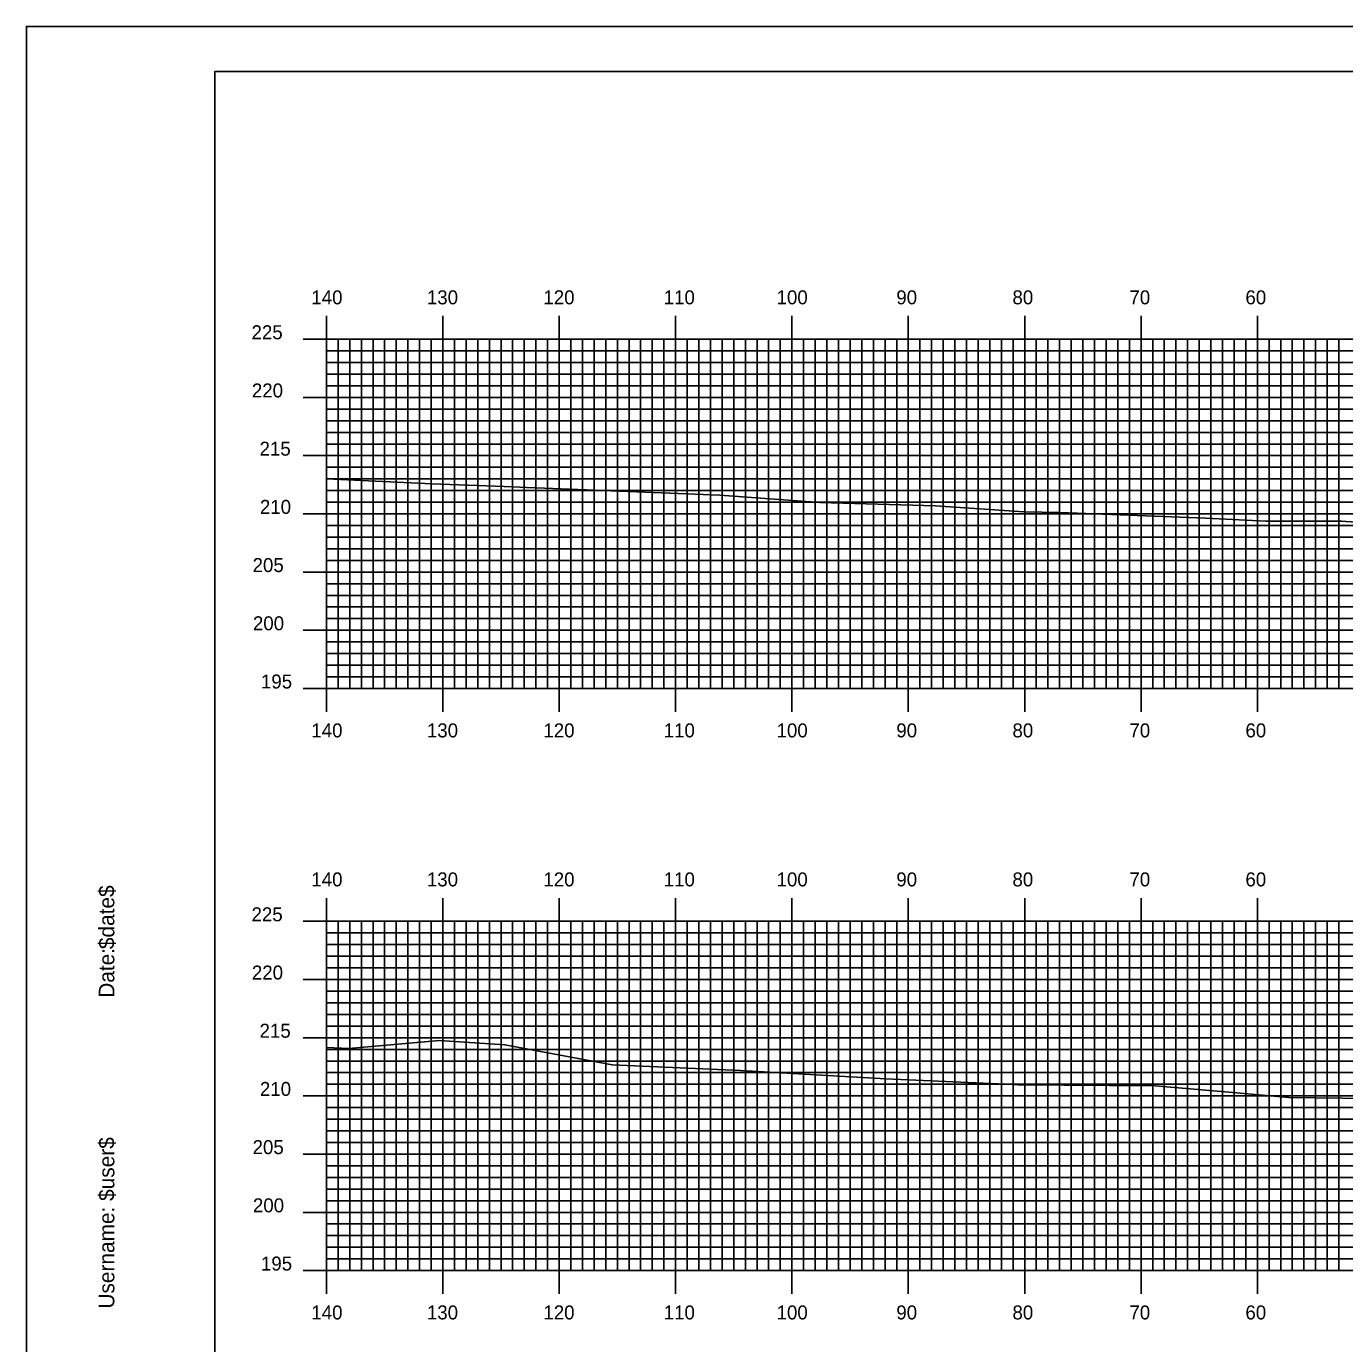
# Model space of a CAD drawing. Extents: x 1805471 to 1805814, y 442591 to 442811.
# Drawn here: x 1805470.9 to 1805584.2, y 442697.4 to 442810.5 of the extents above; entities that cross this region are included whole.
import ezdxf

# ---------------------------------------------------------------- set-up
doc = ezdxf.new("R2010")
doc.units = 0
for name, color, linetype in [('BORDER', 7, 'Continuous'), ('H_V ANNOTATION', 7, 'Continuous'), ('MAJOR', 7, 'Continuous'), ('MINOR', 7, 'Continuous'), ('PLOT BOUNDARY', 7, 'Continuous'), ('S_Roadway_Centerline', 7, 'Continuous')]:
    doc.layers.add(name, color=color, linetype=linetype)

msp = doc.modelspace()

# ---------------------------------------------------------------- linework, layer by layer
at = {"layer": 'BORDER'}
msp.add_lwpolyline([(1805487.11, 442596.67), (1805807.11, 442596.67), (1805807.11, 442806.67), (1805487.11, 442806.67)], close=True, dxfattribs=at)
at = {"layer": 'MAJOR'}
for p, q in [((1805496.71, 442785.67), (1805496.71, 442783.67)), ((1805506.71, 442785.67), (1805506.71, 442783.67)), ((1805516.71, 442785.67), (1805516.71, 442783.67)), ((1805526.71, 442785.67), (1805526.71, 442783.67)), ((1805536.71, 442785.67), (1805536.71, 442783.67)), ((1805546.71, 442785.67), (1805546.71, 442783.67)), ((1805556.71, 442785.67), (1805556.71, 442783.67)), ((1805566.71, 442785.67), (1805566.71, 442783.67)), ((1805576.71, 442785.67), (1805576.71, 442783.67)), ((1805494.7, 442783.67), (1805496.71, 442783.67)), ((1805496.71, 442783.67), (1805776.71, 442783.67)), ((1805496.71, 442753.67), (1805496.71, 442783.67)), ((1805496.71, 442753.67), (1805496.71, 442783.67)), ((1805496.71, 442783.67), (1805776.71, 442783.67)), ((1805506.71, 442753.67), (1805506.71, 442783.67)), ((1805516.71, 442753.67), (1805516.71, 442783.67)), ((1805526.71, 442753.67), (1805526.71, 442783.67)), ((1805536.71, 442753.67), (1805536.71, 442783.67)), ((1805546.71, 442753.67), (1805546.71, 442783.67)), ((1805556.71, 442753.67), (1805556.71, 442783.67)), ((1805566.71, 442753.67), (1805566.71, 442783.67)), ((1805576.71, 442753.67), (1805576.71, 442783.67)), ((1805494.7, 442778.67), (1805496.71, 442778.67)), ((1805496.71, 442778.67), (1805776.71, 442778.67)), ((1805494.7, 442773.67), (1805496.71, 442773.67)), ((1805496.71, 442773.67), (1805776.71, 442773.67)), ((1805494.7, 442768.67), (1805496.71, 442768.67)), ((1805496.71, 442768.67), (1805776.71, 442768.67)), ((1805494.7, 442763.67), (1805496.71, 442763.67)), ((1805496.71, 442763.67), (1805776.71, 442763.67)), ((1805494.7, 442758.67), (1805496.71, 442758.67)), ((1805496.71, 442758.67), (1805776.71, 442758.67)), ((1805494.7, 442753.67), (1805496.71, 442753.67)), ((1805496.71, 442753.67), (1805776.71, 442753.67)), ((1805496.71, 442753.67), (1805776.71, 442753.67)), ((1805496.71, 442751.66), (1805496.71, 442753.67)), ((1805506.71, 442751.66), (1805506.71, 442753.67)), ((1805516.71, 442751.66), (1805516.71, 442753.67)), ((1805526.71, 442751.66), (1805526.71, 442753.67)), ((1805536.71, 442751.66), (1805536.71, 442753.67)), ((1805546.71, 442751.66), (1805546.71, 442753.67)), ((1805556.71, 442751.66), (1805556.71, 442753.67)), ((1805566.71, 442751.66), (1805566.71, 442753.67)), ((1805576.71, 442751.66), (1805576.71, 442753.67)), ((1805496.71, 442735.67), (1805496.71, 442733.67)), ((1805506.71, 442735.67), (1805506.71, 442733.67)), ((1805516.71, 442735.67), (1805516.71, 442733.67)), ((1805526.71, 442735.67), (1805526.71, 442733.67)), ((1805536.71, 442735.67), (1805536.71, 442733.67)), ((1805546.71, 442735.67), (1805546.71, 442733.67)), ((1805556.71, 442735.67), (1805556.71, 442733.67)), ((1805566.71, 442735.67), (1805566.71, 442733.67)), ((1805576.71, 442735.67), (1805576.71, 442733.67)), ((1805494.7, 442733.67), (1805496.71, 442733.67)), ((1805496.71, 442733.67), (1805776.71, 442733.67)), ((1805496.71, 442703.67), (1805496.71, 442733.67)), ((1805496.71, 442703.67), (1805496.71, 442733.67)), ((1805496.71, 442733.67), (1805776.71, 442733.67)), ((1805506.71, 442703.67), (1805506.71, 442733.67)), ((1805516.71, 442703.67), (1805516.71, 442733.67)), ((1805526.71, 442703.67), (1805526.71, 442733.67)), ((1805536.71, 442703.67), (1805536.71, 442733.67)), ((1805546.71, 442703.67), (1805546.71, 442733.67)), ((1805556.71, 442703.67), (1805556.71, 442733.67)), ((1805566.71, 442703.67), (1805566.71, 442733.67)), ((1805576.71, 442703.67), (1805576.71, 442733.67)), ((1805494.7, 442728.67), (1805496.71, 442728.67)), ((1805496.71, 442728.67), (1805776.71, 442728.67)), ((1805494.7, 442723.67), (1805496.71, 442723.67)), ((1805496.71, 442723.67), (1805776.71, 442723.67)), ((1805494.7, 442718.67), (1805496.71, 442718.67)), ((1805496.71, 442718.67), (1805776.71, 442718.67)), ((1805494.7, 442713.67), (1805496.71, 442713.67)), ((1805496.71, 442713.67), (1805776.71, 442713.67)), ((1805494.7, 442708.67), (1805496.71, 442708.67)), ((1805496.71, 442708.67), (1805776.71, 442708.67)), ((1805494.7, 442703.67), (1805496.71, 442703.67)), ((1805496.71, 442703.67), (1805776.71, 442703.67)), ((1805496.71, 442703.67), (1805776.71, 442703.67)), ((1805496.71, 442701.66), (1805496.71, 442703.67)), ((1805506.71, 442701.66), (1805506.71, 442703.67)), ((1805516.71, 442701.66), (1805516.71, 442703.67)), ((1805526.71, 442701.66), (1805526.71, 442703.67)), ((1805536.71, 442701.66), (1805536.71, 442703.67)), ((1805546.71, 442701.66), (1805546.71, 442703.67)), ((1805556.71, 442701.66), (1805556.71, 442703.67)), ((1805566.71, 442701.66), (1805566.71, 442703.67)), ((1805576.71, 442701.66), (1805576.71, 442703.67))]:
    msp.add_line(p, q, dxfattribs=at)
at = {"layer": 'MINOR'}
for p, q in [((1805497.71, 442753.67), (1805497.71, 442783.67)), ((1805498.71, 442753.67), (1805498.71, 442783.67)), ((1805499.71, 442753.67), (1805499.71, 442783.67)), ((1805500.71, 442753.67), (1805500.71, 442783.67)), ((1805501.71, 442753.67), (1805501.71, 442783.67)), ((1805502.71, 442753.67), (1805502.71, 442783.67)), ((1805503.71, 442753.67), (1805503.71, 442783.67)), ((1805504.71, 442753.67), (1805504.71, 442783.67)), ((1805505.71, 442753.67), (1805505.71, 442783.67)), ((1805507.71, 442753.67), (1805507.71, 442783.67)), ((1805508.71, 442753.67), (1805508.71, 442783.67)), ((1805509.71, 442753.67), (1805509.71, 442783.67)), ((1805510.71, 442753.67), (1805510.71, 442783.67)), ((1805511.71, 442753.67), (1805511.71, 442783.67)), ((1805512.71, 442753.67), (1805512.71, 442783.67)), ((1805513.71, 442753.67), (1805513.71, 442783.67)), ((1805514.71, 442753.67), (1805514.71, 442783.67)), ((1805515.71, 442753.67), (1805515.71, 442783.67)), ((1805517.71, 442753.67), (1805517.71, 442783.67)), ((1805518.71, 442753.67), (1805518.71, 442783.67)), ((1805519.71, 442753.67), (1805519.71, 442783.67)), ((1805520.71, 442753.67), (1805520.71, 442783.67)), ((1805521.71, 442753.67), (1805521.71, 442783.67)), ((1805522.71, 442753.67), (1805522.71, 442783.67)), ((1805523.71, 442753.67), (1805523.71, 442783.67)), ((1805524.71, 442753.67), (1805524.71, 442783.67)), ((1805525.71, 442753.67), (1805525.71, 442783.67)), ((1805527.71, 442753.67), (1805527.71, 442783.67)), ((1805528.71, 442753.67), (1805528.71, 442783.67)), ((1805529.71, 442753.67), (1805529.71, 442783.67)), ((1805530.71, 442753.67), (1805530.71, 442783.67)), ((1805531.71, 442753.67), (1805531.71, 442783.67)), ((1805532.71, 442753.67), (1805532.71, 442783.67)), ((1805533.71, 442753.67), (1805533.71, 442783.67)), ((1805534.71, 442753.67), (1805534.71, 442783.67)), ((1805535.71, 442753.67), (1805535.71, 442783.67)), ((1805537.71, 442753.67), (1805537.71, 442783.67)), ((1805538.71, 442753.67), (1805538.71, 442783.67)), ((1805539.71, 442753.67), (1805539.71, 442783.67)), ((1805540.71, 442753.67), (1805540.71, 442783.67)), ((1805541.71, 442753.67), (1805541.71, 442783.67)), ((1805542.71, 442753.67), (1805542.71, 442783.67)), ((1805543.71, 442753.67), (1805543.71, 442783.67)), ((1805544.71, 442753.67), (1805544.71, 442783.67)), ((1805545.71, 442753.67), (1805545.71, 442783.67)), ((1805547.71, 442753.67), (1805547.71, 442783.67)), ((1805548.71, 442753.67), (1805548.71, 442783.67)), ((1805549.71, 442753.67), (1805549.71, 442783.67)), ((1805550.71, 442753.67), (1805550.71, 442783.67)), ((1805551.71, 442753.67), (1805551.71, 442783.67)), ((1805552.71, 442753.67), (1805552.71, 442783.67)), ((1805553.71, 442753.67), (1805553.71, 442783.67)), ((1805554.71, 442753.67), (1805554.71, 442783.67)), ((1805555.71, 442753.67), (1805555.71, 442783.67)), ((1805557.71, 442753.67), (1805557.71, 442783.67)), ((1805558.71, 442753.67), (1805558.71, 442783.67)), ((1805559.71, 442753.67), (1805559.71, 442783.67)), ((1805560.71, 442753.67), (1805560.71, 442783.67)), ((1805561.71, 442753.67), (1805561.71, 442783.67)), ((1805562.71, 442753.67), (1805562.71, 442783.67)), ((1805563.71, 442753.67), (1805563.71, 442783.67)), ((1805564.71, 442753.67), (1805564.71, 442783.67)), ((1805565.71, 442753.67), (1805565.71, 442783.67)), ((1805567.71, 442753.67), (1805567.71, 442783.67)), ((1805568.71, 442753.67), (1805568.71, 442783.67)), ((1805569.71, 442753.67), (1805569.71, 442783.67)), ((1805570.71, 442753.67), (1805570.71, 442783.67)), ((1805571.71, 442753.67), (1805571.71, 442783.67)), ((1805572.71, 442753.67), (1805572.71, 442783.67)), ((1805573.71, 442753.67), (1805573.71, 442783.67)), ((1805574.71, 442753.67), (1805574.71, 442783.67)), ((1805575.71, 442753.67), (1805575.71, 442783.67)), ((1805577.71, 442753.67), (1805577.71, 442783.67)), ((1805578.71, 442753.67), (1805578.71, 442783.67)), ((1805579.71, 442753.67), (1805579.71, 442783.67)), ((1805580.71, 442753.67), (1805580.71, 442783.67)), ((1805581.71, 442753.67), (1805581.71, 442783.67)), ((1805582.71, 442753.67), (1805582.71, 442783.67)), ((1805583.71, 442753.67), (1805583.71, 442783.67)), ((1805496.71, 442782.67), (1805776.71, 442782.67)), ((1805496.71, 442782.67), (1805498.71, 442782.67)), ((1805496.71, 442781.67), (1805776.71, 442781.67)), ((1805496.71, 442781.67), (1805498.71, 442781.67)), ((1805496.71, 442780.67), (1805776.71, 442780.67)), ((1805496.71, 442780.67), (1805498.71, 442780.67)), ((1805496.71, 442779.67), (1805776.71, 442779.67)), ((1805496.71, 442779.67), (1805498.71, 442779.67)), ((1805496.71, 442777.67), (1805776.71, 442777.67)), ((1805496.71, 442777.67), (1805498.71, 442777.67)), ((1805496.71, 442776.67), (1805776.71, 442776.67)), ((1805496.71, 442776.67), (1805498.71, 442776.67)), ((1805496.71, 442775.67), (1805776.71, 442775.67)), ((1805496.71, 442775.67), (1805498.71, 442775.67)), ((1805496.71, 442774.67), (1805776.71, 442774.67)), ((1805496.71, 442774.67), (1805498.71, 442774.67)), ((1805496.71, 442772.67), (1805776.71, 442772.67)), ((1805496.71, 442772.67), (1805498.71, 442772.67)), ((1805496.71, 442771.67), (1805776.71, 442771.67)), ((1805496.71, 442771.67), (1805498.71, 442771.67)), ((1805496.71, 442770.67), (1805776.71, 442770.67)), ((1805496.71, 442770.67), (1805498.71, 442770.67)), ((1805496.71, 442769.67), (1805776.71, 442769.67)), ((1805496.71, 442769.67), (1805498.71, 442769.67)), ((1805496.71, 442767.67), (1805776.71, 442767.67)), ((1805496.71, 442767.67), (1805498.71, 442767.67)), ((1805496.71, 442766.67), (1805776.71, 442766.67)), ((1805496.71, 442766.67), (1805498.71, 442766.67)), ((1805496.71, 442765.67), (1805776.71, 442765.67)), ((1805496.71, 442765.67), (1805498.71, 442765.67)), ((1805496.71, 442764.67), (1805776.71, 442764.67)), ((1805496.71, 442764.67), (1805498.71, 442764.67)), ((1805496.71, 442762.67), (1805776.71, 442762.67)), ((1805496.71, 442762.67), (1805498.71, 442762.67)), ((1805496.71, 442761.67), (1805776.71, 442761.67)), ((1805496.71, 442761.67), (1805498.71, 442761.67)), ((1805496.71, 442760.67), (1805776.71, 442760.67)), ((1805496.71, 442760.67), (1805498.71, 442760.67)), ((1805496.71, 442759.67), (1805776.71, 442759.67)), ((1805496.71, 442759.67), (1805498.71, 442759.67)), ((1805496.71, 442757.67), (1805776.71, 442757.67)), ((1805496.71, 442757.67), (1805498.71, 442757.67)), ((1805496.71, 442756.67), (1805776.71, 442756.67)), ((1805496.71, 442756.67), (1805498.71, 442756.67)), ((1805496.71, 442755.67), (1805776.71, 442755.67)), ((1805496.71, 442755.67), (1805498.71, 442755.67)), ((1805496.71, 442754.67), (1805776.71, 442754.67)), ((1805496.71, 442754.67), (1805498.71, 442754.67)), ((1805497.71, 442703.67), (1805497.71, 442733.67)), ((1805498.71, 442703.67), (1805498.71, 442733.67)), ((1805499.71, 442703.67), (1805499.71, 442733.67)), ((1805500.71, 442703.67), (1805500.71, 442733.67)), ((1805501.71, 442703.67), (1805501.71, 442733.67)), ((1805502.71, 442703.67), (1805502.71, 442733.67)), ((1805503.71, 442703.67), (1805503.71, 442733.67)), ((1805504.71, 442703.67), (1805504.71, 442733.67)), ((1805505.71, 442703.67), (1805505.71, 442733.67)), ((1805507.71, 442703.67), (1805507.71, 442733.67)), ((1805508.71, 442703.67), (1805508.71, 442733.67)), ((1805509.71, 442703.67), (1805509.71, 442733.67)), ((1805510.71, 442703.67), (1805510.71, 442733.67)), ((1805511.71, 442703.67), (1805511.71, 442733.67)), ((1805512.71, 442703.67), (1805512.71, 442733.67)), ((1805513.71, 442703.67), (1805513.71, 442733.67)), ((1805514.71, 442703.67), (1805514.71, 442733.67)), ((1805515.71, 442703.67), (1805515.71, 442733.67)), ((1805517.71, 442703.67), (1805517.71, 442733.67)), ((1805518.71, 442703.67), (1805518.71, 442733.67)), ((1805519.71, 442703.67), (1805519.71, 442733.67)), ((1805520.71, 442703.67), (1805520.71, 442733.67)), ((1805521.71, 442703.67), (1805521.71, 442733.67)), ((1805522.71, 442703.67), (1805522.71, 442733.67)), ((1805523.71, 442703.67), (1805523.71, 442733.67)), ((1805524.71, 442703.67), (1805524.71, 442733.67)), ((1805525.71, 442703.67), (1805525.71, 442733.67)), ((1805527.71, 442703.67), (1805527.71, 442733.67)), ((1805528.71, 442703.67), (1805528.71, 442733.67)), ((1805529.71, 442703.67), (1805529.71, 442733.67)), ((1805530.71, 442703.67), (1805530.71, 442733.67)), ((1805531.71, 442703.67), (1805531.71, 442733.67)), ((1805532.71, 442703.67), (1805532.71, 442733.67)), ((1805533.71, 442703.67), (1805533.71, 442733.67)), ((1805534.71, 442703.67), (1805534.71, 442733.67)), ((1805535.71, 442703.67), (1805535.71, 442733.67)), ((1805537.71, 442703.67), (1805537.71, 442733.67)), ((1805538.71, 442703.67), (1805538.71, 442733.67)), ((1805539.71, 442703.67), (1805539.71, 442733.67)), ((1805540.71, 442703.67), (1805540.71, 442733.67)), ((1805541.71, 442703.67), (1805541.71, 442733.67)), ((1805542.71, 442703.67), (1805542.71, 442733.67)), ((1805543.71, 442703.67), (1805543.71, 442733.67)), ((1805544.71, 442703.67), (1805544.71, 442733.67)), ((1805545.71, 442703.67), (1805545.71, 442733.67)), ((1805547.71, 442703.67), (1805547.71, 442733.67)), ((1805548.71, 442703.67), (1805548.71, 442733.67)), ((1805549.71, 442703.67), (1805549.71, 442733.67)), ((1805550.71, 442703.67), (1805550.71, 442733.67)), ((1805551.71, 442703.67), (1805551.71, 442733.67)), ((1805552.71, 442703.67), (1805552.71, 442733.67)), ((1805553.71, 442703.67), (1805553.71, 442733.67)), ((1805554.71, 442703.67), (1805554.71, 442733.67)), ((1805555.71, 442703.67), (1805555.71, 442733.67)), ((1805557.71, 442703.67), (1805557.71, 442733.67)), ((1805558.71, 442703.67), (1805558.71, 442733.67)), ((1805559.71, 442703.67), (1805559.71, 442733.67)), ((1805560.71, 442703.67), (1805560.71, 442733.67)), ((1805561.71, 442703.67), (1805561.71, 442733.67)), ((1805562.71, 442703.67), (1805562.71, 442733.67)), ((1805563.71, 442703.67), (1805563.71, 442733.67)), ((1805564.71, 442703.67), (1805564.71, 442733.67)), ((1805565.71, 442703.67), (1805565.71, 442733.67)), ((1805567.71, 442703.67), (1805567.71, 442733.67)), ((1805568.71, 442703.67), (1805568.71, 442733.67)), ((1805569.71, 442703.67), (1805569.71, 442733.67)), ((1805570.71, 442703.67), (1805570.71, 442733.67)), ((1805571.71, 442703.67), (1805571.71, 442733.67)), ((1805572.71, 442703.67), (1805572.71, 442733.67)), ((1805573.71, 442703.67), (1805573.71, 442733.67)), ((1805574.71, 442703.67), (1805574.71, 442733.67)), ((1805575.71, 442703.67), (1805575.71, 442733.67)), ((1805577.71, 442703.67), (1805577.71, 442733.67)), ((1805578.71, 442703.67), (1805578.71, 442733.67)), ((1805579.71, 442703.67), (1805579.71, 442733.67)), ((1805580.71, 442703.67), (1805580.71, 442733.67)), ((1805581.71, 442703.67), (1805581.71, 442733.67)), ((1805582.71, 442703.67), (1805582.71, 442733.67)), ((1805583.71, 442703.67), (1805583.71, 442733.67)), ((1805496.71, 442732.67), (1805776.71, 442732.67)), ((1805496.71, 442732.67), (1805498.71, 442732.67)), ((1805496.71, 442731.67), (1805776.71, 442731.67)), ((1805496.71, 442731.67), (1805498.71, 442731.67)), ((1805496.71, 442730.67), (1805776.71, 442730.67)), ((1805496.71, 442730.67), (1805498.71, 442730.67)), ((1805496.71, 442729.67), (1805776.71, 442729.67)), ((1805496.71, 442729.67), (1805498.71, 442729.67)), ((1805496.71, 442727.67), (1805776.71, 442727.67)), ((1805496.71, 442727.67), (1805498.71, 442727.67)), ((1805496.71, 442726.67), (1805776.71, 442726.67)), ((1805496.71, 442726.67), (1805498.71, 442726.67)), ((1805496.71, 442725.67), (1805776.71, 442725.67)), ((1805496.71, 442725.67), (1805498.71, 442725.67)), ((1805496.71, 442724.67), (1805776.71, 442724.67)), ((1805496.71, 442724.67), (1805498.71, 442724.67)), ((1805496.71, 442722.67), (1805776.71, 442722.67)), ((1805496.71, 442722.67), (1805498.71, 442722.67)), ((1805496.71, 442721.67), (1805776.71, 442721.67)), ((1805496.71, 442721.67), (1805498.71, 442721.67)), ((1805496.71, 442720.67), (1805776.71, 442720.67)), ((1805496.71, 442720.67), (1805498.71, 442720.67)), ((1805496.71, 442719.67), (1805776.71, 442719.67)), ((1805496.71, 442719.67), (1805498.71, 442719.67)), ((1805496.71, 442717.67), (1805776.71, 442717.67)), ((1805496.71, 442717.67), (1805498.71, 442717.67)), ((1805496.71, 442716.67), (1805776.71, 442716.67)), ((1805496.71, 442716.67), (1805498.71, 442716.67)), ((1805496.71, 442715.67), (1805776.71, 442715.67)), ((1805496.71, 442715.67), (1805498.71, 442715.67)), ((1805496.71, 442714.67), (1805776.71, 442714.67)), ((1805496.71, 442714.67), (1805498.71, 442714.67)), ((1805496.71, 442712.67), (1805776.71, 442712.67)), ((1805496.71, 442712.67), (1805498.71, 442712.67)), ((1805496.71, 442711.67), (1805776.71, 442711.67)), ((1805496.71, 442711.67), (1805498.71, 442711.67)), ((1805496.71, 442710.67), (1805776.71, 442710.67)), ((1805496.71, 442710.67), (1805498.71, 442710.67)), ((1805496.71, 442709.67), (1805776.71, 442709.67)), ((1805496.71, 442709.67), (1805498.71, 442709.67)), ((1805496.71, 442707.67), (1805776.71, 442707.67)), ((1805496.71, 442707.67), (1805498.71, 442707.67)), ((1805496.71, 442706.67), (1805776.71, 442706.67)), ((1805496.71, 442706.67), (1805498.71, 442706.67)), ((1805496.71, 442705.67), (1805776.71, 442705.67)), ((1805496.71, 442705.67), (1805498.71, 442705.67)), ((1805496.71, 442704.67), (1805776.71, 442704.67)), ((1805496.71, 442704.67), (1805498.71, 442704.67))]:
    msp.add_line(p, q, dxfattribs=at)
at = {"layer": 'PLOT BOUNDARY'}
msp.add_lwpolyline([(1805470.92, 442590.55), (1805810.92, 442590.55), (1805810.92, 442810.55), (1805470.92, 442810.55)], close=True, dxfattribs=at)
at = {"layer": 'S_Roadway_Centerline'}
for points in [[(1805496.71, 442771.69), (1805505.76, 442771.26), (1805512.74, 442771), (1805513.89, 442770.94), (1805515.46, 442770.88), (1805530.5, 442770.29), (1805539.11, 442769.66), (1805549.05, 442769.37), (1805556.63, 442768.84), (1805559.72, 442768.78), (1805564.91, 442768.6), (1805572.28, 442768.31), (1805577.44, 442768.05), (1805583.93, 442768.03), (1805591.82, 442767.49)], [(1805496.71, 442722.82), (1805498.63, 442722.75), (1805506.41, 442723.43), (1805512.05, 442723.07), (1805521.26, 442721.33), (1805531.64, 442720.87), (1805531.8, 442720.87), (1805544.79, 442720.15), (1805555.73, 442719.64), (1805556.15, 442719.63), (1805567.92, 442719.53), (1805574.92, 442718.93), (1805579.42, 442718.53), (1805597.92, 442718.31)]]:
    msp.add_lwpolyline(points, dxfattribs=at)

# ---------------------------------------------------------------- texts
at = {"layer": 'BORDER'}
for s, p in [('$date$', (1805478.48, 442731.28)), ('Date:', (1805478.48, 442727.1)), ('$user$', (1805478.48, 442709.65)), ('Username:', (1805478.48, 442700.4))]:
    msp.add_text(s, height=1.339, rotation=90, dxfattribs=at).set_placement(p)
at = {"layer": 'H_V ANNOTATION'}
for s, p in [('140', (1805495.41, 442786.67)), ('130', (1805505.34, 442786.67)), ('120', (1805515.35, 442786.67)), ('110', (1805525.69, 442786.67)), ('100', (1805535.39, 442786.67)), ('90', (1805545.68, 442786.67)), ('80', (1805555.66, 442786.67)), ('70', (1805565.71, 442786.67)), ('60', (1805575.68, 442786.67)), ('225', (1805490.27, 442783.67)), ('220', (1805490.3, 442778.67)), ('215', (1805490.96, 442773.67)), ('210', (1805490.99, 442768.67)), ('205', (1805490.36, 442763.67)), ('200', (1805490.39, 442758.67)), ('195', (1805491.08, 442753.67)), ('140', (1805495.41, 442749.47)), ('130', (1805505.34, 442749.47)), ('120', (1805515.35, 442749.47)), ('110', (1805525.69, 442749.47)), ('100', (1805535.39, 442749.47)), ('90', (1805545.68, 442749.47)), ('80', (1805555.66, 442749.47)), ('70', (1805565.71, 442749.47)), ('60', (1805575.68, 442749.47)), ('140', (1805495.41, 442736.67)), ('130', (1805505.34, 442736.67)), ('120', (1805515.35, 442736.67)), ('110', (1805525.69, 442736.67)), ('100', (1805535.39, 442736.67)), ('90', (1805545.68, 442736.67)), ('80', (1805555.66, 442736.67)), ('70', (1805565.71, 442736.67)), ('60', (1805575.68, 442736.67)), ('225', (1805490.27, 442733.67)), ('220', (1805490.3, 442728.67)), ('215', (1805490.96, 442723.67)), ('210', (1805490.99, 442718.67)), ('205', (1805490.36, 442713.67)), ('200', (1805490.39, 442708.67)), ('195', (1805491.08, 442703.67)), ('140', (1805495.41, 442699.47)), ('130', (1805505.34, 442699.47)), ('120', (1805515.35, 442699.47)), ('110', (1805525.69, 442699.47)), ('100', (1805535.39, 442699.47)), ('90', (1805545.68, 442699.47)), ('80', (1805555.66, 442699.47)), ('70', (1805565.71, 442699.47)), ('60', (1805575.68, 442699.47))]:
    msp.add_text(s, height=1.2, dxfattribs=at).set_placement(p)
at = {"layer": 'MAJOR'}
for p in [(1805496.7, 442753.67), (1805496.7, 442703.67)]:
    msp.add_text('-', height=0.012, dxfattribs=at).set_placement(p)

doc.saveas('drawing.dxf')
